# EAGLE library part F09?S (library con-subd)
SUB-D
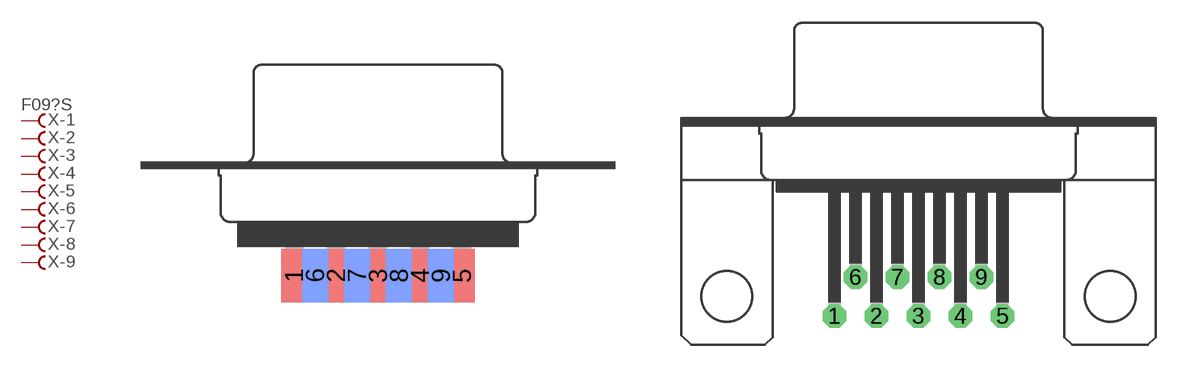
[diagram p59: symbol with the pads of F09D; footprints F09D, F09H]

Designator prefix X; gates -1=FV -2=F -3=F -4=F -5=F -6=F -7=F -8=F -9=F

## F09DS (OC_FARNELL: unknown; OC_NEWARK: unknown)  [F09D]
1  -1:F  pas
2  -2:F  pas
3  -3:F  pas
4  -4:F  pas
5  -5:F  pas
6  -6:F  pas
7  -7:F  pas
8  -8:F  pas
9  -9:F  pas

## F09HS (OC_FARNELL: unknown; OC_NEWARK: unknown)  [F09H]
Pads as for F09D

## F09HPS (OC_FARNELL: unknown; OC_NEWARK: unknown)  [F09HP]
Pads as for F09D

## F09VS (OC_FARNELL: unknown; OC_NEWARK: unknown)  [F09V]
Pads as for F09D

## F09VPS (OC_FARNELL: unknown; OC_NEWARK: unknown)  [F09VP]
Pads as for F09D

## F09VBS (OC_FARNELL: unknown; OC_NEWARK: unknown)  [F09VB]
Pads as for F09D

## F09.590S (OC_FARNELL: unknown; OC_NEWARK: unknown)  [177-009-FEMALE]
Pads as for F09D

## Footprint F09D (pad centres in mm)
SUB-D
smd 1.7 x 3.5: 1 -5.486,-6.045; 2 -2.743,-6.045; 3 0,-6.045; 4 2.743,-6.045; 5 5.486,-6.045
smd 1.7 x 3.5 bottom: 6 -4.115,-6.045; 7 -1.372,-6.045; 8 1.372,-6.045; 9 4.115,-6.045

## Footprint F09H (pad centres in mm)
SUB-D
drill 1.016 octagon: 1 -5.486,-1.27; 2 -2.743,-1.27; 3 0,-1.27; 4 2.743,-1.27; 5 5.486,-1.27; 6 -4.115,1.27; 7 -1.372,1.27; 8 1.372,1.27; 9 4.115,1.27
hole 3.302 at -12.522,0
hole 3.302 at 12.522,0

## Footprint F09HP (pad centres in mm)
SUB-D
drill 1.016 octagon: 1 -5.486,-1.27; 2 -2.743,-1.27; 3 0,-1.27; 4 2.743,-1.27; 5 5.486,-1.27; 6 -4.115,1.27; 7 -1.372,1.27; 8 1.372,1.27; 9 4.115,1.27
drill 3.302 pad 5.08 round: G1 -12.522,0; G2 12.522,0

## Footprint F09V (pad centres in mm)
SUB-D
drill 1.016 octagon: 1 5.486,1.422; 2 2.743,1.422; 3 0,1.422; 4 -2.743,1.422; 5 -5.486,1.422; 6 4.115,-1.422; 7 1.372,-1.422; 8 -1.372,-1.422; 9 -4.115,-1.422
hole 3.302 at -12.522,0
hole 3.302 at 12.522,0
